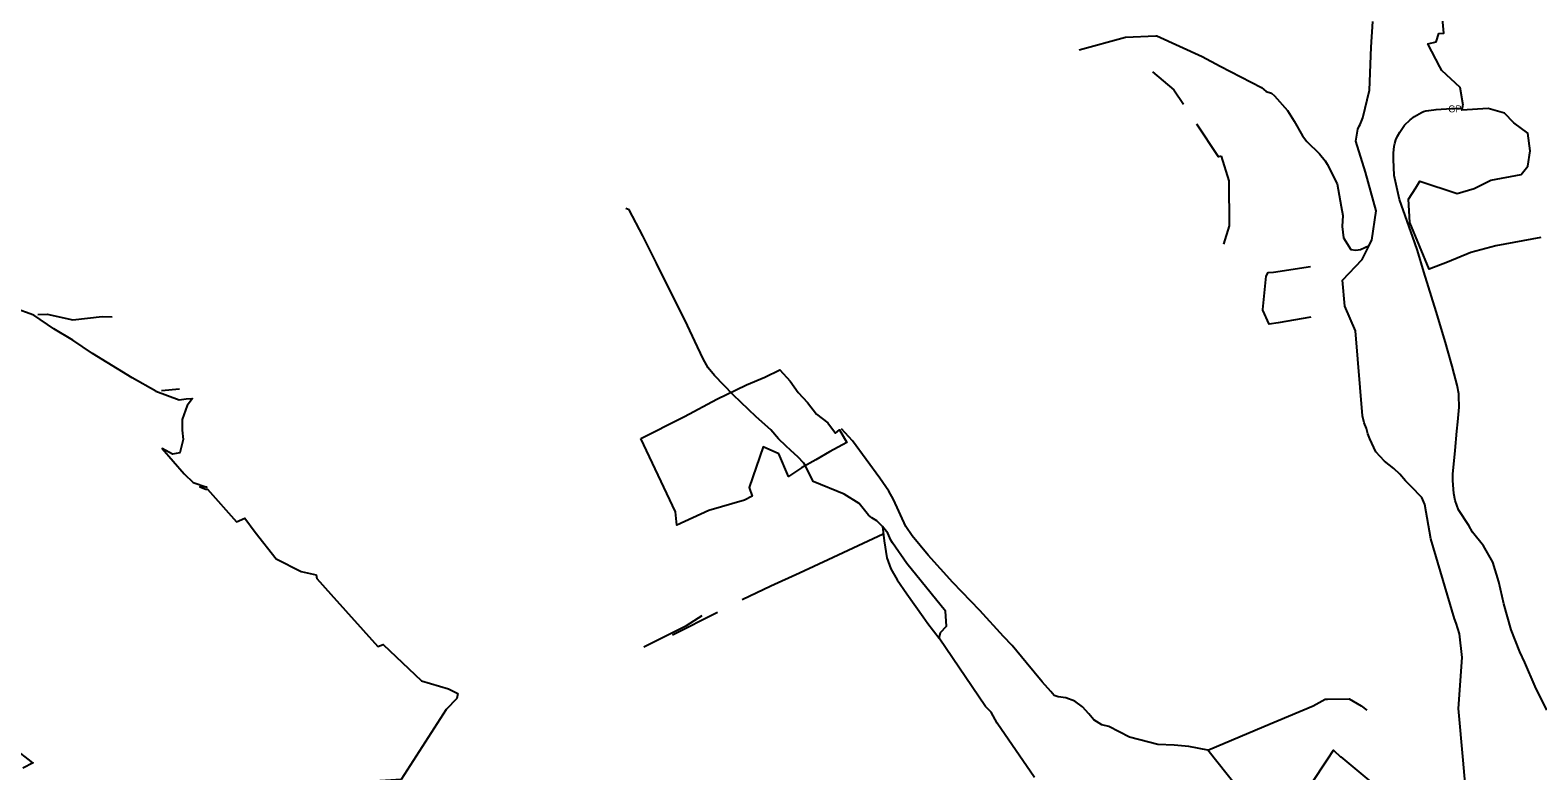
# Model space of a CAD drawing. Extents: x -617038 to -609441, y -1109294 to -1104285.
# Drawn here: x -614251 to -612071, y -1107029 to -1105958 of the extents above; entities that cross this region are included whole.
import ezdxf

# ---------------------------------------------------------------- set-up
doc = ezdxf.new("R2010")
doc.units = 0
for name, color, linetype in [('CESTY', 7, 'Continuous'), ('GRA_ZV', 7, 'Continuous'), ('LES_ZV', 7, 'Continuous'), ('Level 255', 7, 'Continuous'), ('OVNE_SET', 7, 'Continuous'), ('OVNI_PRE', 7, 'Continuous'), ('OVNI_SET', 7, 'Continuous'), ('VODA', 7, 'Continuous')]:
    doc.layers.add(name, color=color, linetype=linetype)

msp = doc.modelspace()

# ---------------------------------------------------------------- linework, layer by layer
at = {"layer": 'CESTY'}
msp.add_lwpolyline([(-612057.7, -1106941.7), (-612074.6, -1106907.4), (-612089.8, -1106872.6), (-612097, -1106857), (-612109.5, -1106825.5), (-612119.9, -1106787.6), (-612127.1, -1106755.8), (-612135.8, -1106727.5), (-612149.5, -1106703.8), (-612165.3, -1106683.9), (-612170.8, -1106674.6), (-612185.7, -1106651.7), (-612190.6, -1106638.4), (-612192.5, -1106628.2), (-612193.8, -1106609.6), (-612194, -1106599.7), (-612192.5, -1106585.6), (-612190.6, -1106566), (-612187.9, -1106538.2), (-612186.6, -1106524.7), (-612184.4, -1106503.5), (-612185.2, -1106487.1), (-612185.3, -1106484.1), (-612187.6, -1106471.5), (-612192, -1106455.2), (-612195, -1106444.1), (-612201.1, -1106422), (-612204.4, -1106409.9), (-612218.1, -1106364.7), (-612235.9, -1106307.3), (-612244.8, -1106276.8), (-612248.9, -1106265.8), (-612270.9, -1106202.7), (-612278.6, -1106168.2), (-612279.5, -1106144.5), (-612279.4, -1106135.7), (-612278.4, -1106125.7), (-612277.7, -1106121.7), (-612276.2, -1106116.7), (-612274, -1106111.5), (-612270.6, -1106105.6), (-612263.6, -1106095.6), (-612255.7, -1106087.6), (-612249.2, -1106082.9), (-612242.3, -1106078.8), (-612239, -1106077.2), (-612236, -1106075.8), (-612233, -1106074.8), (-612228.7, -1106074.2), (-612217.7, -1106072.8), (-612195.7, -1106071.3), (-612179.8, -1106070.8)], dxfattribs=at)
at = {"layer": 'GRA_ZV'}
msp.add_lwpolyline([(-613367.5, -1106548.7), (-613307.6, -1106518.4), (-613304.5, -1106516.9), (-613258, -1106491.5), (-613214.8, -1106471.1), (-613188.5, -1106460.1), (-613166.7, -1106449.3), (-613152, -1106465.7), (-613140.2, -1106482), (-613126.8, -1106496.4), (-613114, -1106513.5), (-613097.6, -1106526.2), (-613086.1, -1106540.8), (-613080.4, -1106536.1), (-613070, -1106554.5), (-613095.2, -1106568), (-613114.6, -1106579.3), (-613135.6, -1106591.1), (-613154.1, -1106603.4), (-613168.3, -1106570.9), (-613190.9, -1106560.8), (-613211.3, -1106619.6), (-613207, -1106632.1), (-613217.7, -1106637.6), (-613269.2, -1106652.7), (-613315.8, -1106674), (-613317.4, -1106654.6), (-613367.5, -1106548.7)], dxfattribs=at)
at = {"layer": 'LES_ZV'}
for p, q in [((-612453.1, -1106308), (-612399.4, -1106300)), ((-614146.4, -1106372.1), (-614132.2, -1106372.4)), ((-612398.9, -1106373.2), (-612446.2, -1106381.5)), ((-614060.7, -1106479.3), (-614034.7, -1106476.7)), ((-613089.5, -1106720.5), (-613017.5, -1106686.4))]:
    msp.add_line(p, q, dxfattribs=at)
for points in [[(-612628.2, -1106018), (-612597.1, -1106044.2), (-612583.4, -1106064.8)], [(-612528.9, -1106140), (-612532.7, -1106141.2), (-612564, -1106094.1)], [(-612528.9, -1106140), (-612517.7, -1106176.1), (-612517, -1106240.8), (-612525.5, -1106267.6)], [(-612446.2, -1106381.5), (-612459.1, -1106383.3), (-612468.4, -1106362.8), (-612468.3, -1106362.1), (-612463.6, -1106314), (-612460.7, -1106308.6), (-612453.1, -1106308)], [(-614239.3, -1106369.2), (-614226.1, -1106368.9), (-614188.7, -1106376.8), (-614146.4, -1106372.1)], [(-613221.1, -1106781.3), (-613179.8, -1106761.8), (-613138.1, -1106742.8), (-613089.5, -1106720.5)], [(-613363.2, -1106850.2), (-613322.9, -1106829.8), (-613301.5, -1106818.9), (-613279, -1106804.6)], [(-613256.8, -1106800.4), (-613257, -1106800.5), (-613322, -1106833.3)]]:
    msp.add_lwpolyline(points, dxfattribs=at)
at = {"layer": 'Level 255'}
msp.add_line((-613256.8, -1106800.4), (-613256.8, -1106800.4), dxfattribs=at)
at = {"layer": 'OVNE_SET'}
for points in [[(-612178.7, -1106066.4), (-612183, -1106040.9), (-612209.8, -1106016.1), (-612212.5, -1106010.9), (-612229.7, -1105977.8), (-612218, -1105974.9), (-612214, -1105963), (-612206.9, -1105962.1), (-612209.5, -1105929.9), (-612216.7, -1105930.8)], [(-612201.3, -1106293.6), (-612228.1, -1106303.8), (-612255.8, -1106236.4), (-612257.7, -1106202.3), (-612247.3, -1106185.9), (-612241.5, -1106176.5), (-612187.7, -1106194), (-612163.1, -1106187.1), (-612138.7, -1106175), (-612094.8, -1106166.5), (-612085.5, -1106154.8), (-612082.2, -1106132.6), (-612085.5, -1106106.8), (-612105.6, -1106092.2), (-612119.2, -1106078.2), (-612142.9, -1106071.3), (-612180.6, -1106073.6), (-612178.7, -1106066.4)], [(-612066.7, -1106258), (-612131.6, -1106269.8), (-612167.7, -1106279.7), (-612201.3, -1106293.6)]]:
    msp.add_lwpolyline(points, dxfattribs=at)
at = {"layer": 'OVNI_PRE'}
msp.add_line((-613633.6, -1106924.5), (-613649, -1106940.4), dxfattribs=at)
at = {"layer": 'OVNI_SET'}
msp.add_line((-613632.5, -1106917.6), (-613633.6, -1106924.5), dxfattribs=at)
for points in [[(-614068.9, -1106480.1), (-614102.9, -1106460.7), (-614160.3, -1106425.8), (-614189.1, -1106406.5), (-614216.6, -1106390.2), (-614245.3, -1106370.2), (-614304.4, -1106349), (-614354.2, -1106330.4), (-614371.5, -1106322.7), (-614395, -1106313.4), (-614437.4, -1106302.7), (-614462.3, -1106299.3), (-614465.5, -1106297.7), (-614476.6, -1106297.4), (-614483.4, -1106297.1), (-614484.6, -1106295.9), (-614489.4, -1106295.6)], [(-614068.9, -1106480.1), (-614035.3, -1106492.5), (-614025, -1106491.3)], [(-614025, -1106491.3), (-614015.9, -1106490.9), (-614023.4, -1106500.9), (-614030.6, -1106520.9), (-614030.7, -1106536.4), (-614029.4, -1106550.1), (-614034.2, -1106569.3), (-614045, -1106571.1), (-614059.9, -1106563.1), (-614027.8, -1106599.7), (-614015.1, -1106612.4), (-613995.1, -1106618.9), (-614005.4, -1106618.7), (-613996.5, -1106621.8), (-613994.2, -1106621.9), (-613952.1, -1106669.2), (-613940.2, -1106664.1), (-613925.2, -1106684.1), (-613895, -1106722.7), (-613858.7, -1106740.9), (-613837.3, -1106745.9), (-613836.3, -1106751), (-613815.7, -1106773.6), (-613748.1, -1106849.4), (-613740.2, -1106846.8), (-613684.6, -1106899), (-613645.6, -1106910.6), (-613632.5, -1106917.6)], [(-613649, -1106940.4), (-613714.2, -1107041.8), (-613744.5, -1107043.7), (-613752.7, -1107046.6)], [(-614273.4, -1106997.6), (-614249.8, -1107015.8), (-614249.6, -1107015.9), (-614246.4, -1107017.9), (-614261.1, -1107025.7)], [(-612409.9, -1107065.2), (-612399.2, -1107049), (-612374.6, -1107011.8), (-612366.4, -1106999.4), (-612355.9, -1107009.5), (-612355.8, -1107008.9), (-612318.1, -1107040.3), (-612303.8, -1107052.2)]]:
    msp.add_lwpolyline(points, dxfattribs=at)
at = {"layer": 'VODA'}
for points in [[(-612173.4, -1107074.5), (-612178.9, -1107013.8), (-612185.8, -1106939.1), (-612180.3, -1106865.3), (-612184.1, -1106831.3), (-612189.1, -1106815.7), (-612191.2, -1106809.3), (-612221.8, -1106707), (-612225.7, -1106693.6), (-612234.1, -1106644), (-612238.6, -1106633.8), (-612240.4, -1106631.9), (-612252.3, -1106620), (-612262.1, -1106609.7), (-612270.4, -1106600.1), (-612278.9, -1106592), (-612292.5, -1106581.4), (-612304.9, -1106568), (-612313.6, -1106549.3), (-612316.8, -1106541.7), (-612318.6, -1106534), (-612322.1, -1106525.8), (-612324.2, -1106516), (-612334.3, -1106392.9), (-612350.1, -1106357.4), (-612353.4, -1106319.7), (-612325.1, -1106289.9), (-612314.9, -1106269.4), (-612313.8, -1106267), (-612311.1, -1106261.9), (-612304.6, -1106219.2), (-612319.9, -1106163.6), (-612333.9, -1106118.7), (-612331.2, -1106101.4), (-612329, -1106096.6), (-612327.9, -1106094.5), (-612324.1, -1106084.7), (-612314.3, -1106044.9), (-612311.8, -1105982.5), (-612309.5, -1105945.6)], [(-612734.2, -1105986.4), (-612667.2, -1105968.1), (-612623.4, -1105966.3), (-612621.5, -1105966.2), (-612556, -1105996), (-612530.3, -1106010.2), (-612470.4, -1106041.1), (-612463.5, -1106046.6), (-612455.8, -1106049.2), (-612451.4, -1106052.9), (-612432.8, -1106074.2), (-612423, -1106089.5), (-612411.1, -1106111), (-612405.1, -1106119), (-612386.8, -1106136.9), (-612378.2, -1106146.8), (-612375.6, -1106151.9), (-612361, -1106180.1), (-612355.3, -1106212.8), (-612353, -1106226), (-612353.8, -1106242.1), (-612352, -1106258.2), (-612341.4, -1106275), (-612334, -1106276.4), (-612327.4, -1106275.1), (-612314.9, -1106269.4)], [(-613018.4, -1106675.8), (-613023.4, -1106670.9), (-613026.7, -1106667.8), (-613033.6, -1106663.4), (-613038.7, -1106659.5), (-613052.1, -1106642.6), (-613073.8, -1106629.1), (-613118.6, -1106610.7), (-613129.6, -1106588.2), (-613132, -1106584.4), (-613140.8, -1106575), (-613150.8, -1106566.2), (-613158.2, -1106559.3), (-613168.9, -1106549), (-613179.7, -1106535.9), (-613201.1, -1106517.1), (-613234.4, -1106485.3), (-613261.1, -1106457.7), (-613270.3, -1106446.4), (-613277.4, -1106433.2), (-613289.6, -1106408), (-613300.1, -1106385), (-613345.2, -1106294.8), (-613365, -1106255.5), (-613384.7, -1106218), (-613389.2, -1106215.8)], [(-612547.8, -1106999.7), (-612575.5, -1106994.2), (-612596.7, -1106992.4), (-612620.4, -1106991.4), (-612633.3, -1106988), (-612661.4, -1106980.6), (-612690.9, -1106965.1), (-612701.3, -1106962.7), (-612712.7, -1106955.8), (-612720.1, -1106946.7), (-612729.1, -1106936.7), (-612740.2, -1106928.7), (-612753.1, -1106924), (-612764.2, -1106922.5), (-612770.2, -1106920.4), (-612774.8, -1106914.6), (-612787.5, -1106900.5), (-612810.4, -1106872.8), (-612830.8, -1106848.3), (-612843.5, -1106835.1), (-612877.8, -1106797.5), (-612916.5, -1106756.7), (-612952.2, -1106717.4), (-612975.5, -1106689.6), (-612984.6, -1106675.7), (-613002.4, -1106636.9), (-613009.4, -1106624.8), (-613022, -1106606.2), (-613061.5, -1106551.8), (-613077.6, -1106534.5)], [(-612798.4, -1107039.2), (-612852.5, -1106960.4), (-612861.3, -1106944.7), (-612869.5, -1106936.3), (-612936.2, -1106837.3), (-612934.4, -1106829.2), (-612925.7, -1106819.9), (-612927.1, -1106798.6), (-612983.1, -1106729.4), (-613004, -1106699.6), (-613006.1, -1106695.7), (-613010.6, -1106685.6), (-613018.4, -1106675.8), (-613015.7, -1106696.6), (-613012.1, -1106721.4), (-613006.3, -1106737.3), (-612997.2, -1106753.2), (-612983, -1106773.5), (-612959.6, -1106806.4), (-612952.8, -1106816.3), (-612936.2, -1106837.3)], [(-612492.2, -1107070.1), (-612547.8, -1106999.7), (-612467.2, -1106965.4), (-612395.9, -1106935.1), (-612378.2, -1106925.7), (-612374.8, -1106925.6), (-612343.6, -1106925.2), (-612326.4, -1106935.2), (-612318.3, -1106941.7)]]:
    msp.add_lwpolyline(points, dxfattribs=at)

# ---------------------------------------------------------------- texts
at = {"layer": 'OVNE_SET'}
msp.add_text('GP', height=10, dxfattribs=at).set_placement((-612200.4, -1106076.8))

doc.saveas('drawing.dxf')
